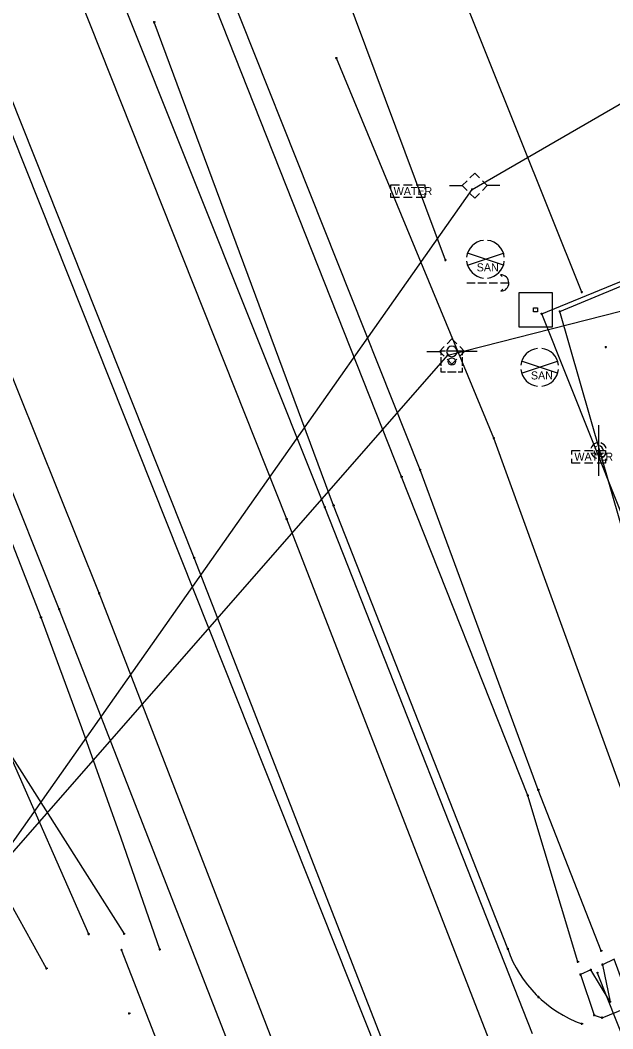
# Model space of a CAD drawing. Extents: x 1954856 to 2011933, y 399149 to 426294.
# Drawn here: x 2004898.7 to 2004969, y 408004.6 to 408124.3 of the extents above; entities that cross this region are included whole.
import ezdxf

# ---------------------------------------------------------------- set-up
doc = ezdxf.new("R2010")
doc.units = 0
for name, color, linetype in [('BankMent_ep', 7, 'Continuous'), ('BaselineSurvey', 7, 'Continuous'), ('ElecAer_ep', 7, 'Continuous'), ('EndTreatMES_ep', 7, 'Continuous'), ('Fence_ep', 7, 'Continuous'), ('FlowLineInvert_ep', 7, 'Continuous'), ('GuyWireAnchor_ep', 7, 'Continuous'), ('MeterWater_ep', 7, 'Continuous'), ('MonumentCC_ep', 7, 'Continuous'), ('PavtAsphalt_ep', 7, 'Continuous'), ('PavtAsphaltCrown_ep', 7, 'Continuous'), ('PipeCulvert_ep', 7, 'Continuous'), ('PointLocator_ep', 7, 'Continuous'), ('PoleElec_ep', 7, 'Continuous'), ('PoleShared_ep', 7, 'Continuous'), ('ShldrPaved_ep', 7, 'Continuous'), ('TelePed_ep', 7, 'Continuous'), ('TreeLineScatter_ep', 7, 'Continuous'), ('ValveCvrSewer_ep', 7, 'Continuous'), ('WaterFct_ep', 7, 'Continuous')]:
    doc.layers.add(name, color=color, linetype=linetype)

msp = doc.modelspace()

# ---------------------------------------------------------------- linework, layer by layer
at = {"layer": 'BankMent_ep'}
for p, q in [((2004935.85, 408066.75), (2004914.58, 408124.08)), ((2004954.86, 408074.74), (2004936.18, 408119.82)), ((2004974.42, 408020.72), (2004954.86, 408074.74)), ((2004956.5, 408014.12), (2004935.85, 408066.75)), ((2004901.81, 408011.79), (2004882.61, 408046.36))]:
    msp.add_line(p, q, dxfattribs=at)
for points in [[(2004915.23, 408014.06), (2004910.66, 408027.24), (2004905.98, 408040.37), (2004901.14, 408053.44), (2004893.86, 408072.1), (2004886.3, 408090.65), (2004878.58, 408109.14), (2004870.82, 408127.61), (2004863.14, 408146.12), (2004851.89, 408174.22), (2004840.96, 408202.44), (2004830.19, 408230.72)], [(2004967.6, 408013.9), (2004960.12, 408032.99), (2004946.12, 408070.97), (2004923.28, 408128.46)], [(2004964.83, 408012.59), (2004958.88, 408032.32), (2004943.91, 408070.15), (2004921.14, 408127.75)], [(2004977.16, 408039.32), (2004962.69, 408089.76), (2005001.33, 408105.83)], [(2004906.8, 408015.87), (2004897.29, 408037.55), (2004911.01, 408015.9)]]:
    msp.add_lwpolyline(points, dxfattribs=at)
msp.add_arc((2004970.17, 408018.84), 14.46, 199.0739, 250.3363, dxfattribs=at)
at = {"layer": 'BaselineSurvey'}
msp.add_line((2004967.71, 407935.04), (2004043.6, 410254.04), dxfattribs=at)
msp.add_line((2004967.71, 407935.04), (2004043.6, 410254.04), dxfattribs=at)
at = {"layer": 'ElecAer_ep'}
for points in [[(2004893.49, 408020.69), (2004952.29, 408104.24), (2005007.14, 408136)], [(2004893.49, 408020.69), (2004949.39, 408084.58), (2005015.19, 408101.35)], [(2004949.39, 408084.58), (2005015.19, 408101.35)]]:
    msp.add_lwpolyline(points, dxfattribs=at)
at = {"layer": 'EndTreatMES_ep'}
msp.add_lwpolyline([(2004969.12, 408012.89), (2004967.74, 408012.24), (2004968.65, 408007.83), (2004966.34, 408011.64), (2004965.13, 408011.07), (2004966.76, 408006.27), (2004967.69, 408005.95), (2004970.5, 408007.07), (2004970.89, 408008.05)], close=True, dxfattribs=at)
at = {"layer": 'Fence_ep'}
for points in [[(2004965.28, 408092.05), (2004946.37, 408139.38), (2004934.99, 408168.84), (2004909.94, 408231.83)], [(2004990.83, 408013.53), (2004960.53, 408089.49), (2005000.44, 408105.86)]]:
    msp.add_lwpolyline(points, dxfattribs=at)
at = {"layer": 'FlowLineInvert_ep'}
for p, q in [((2004910.78, 408013.92), (2004910.6, 408014.09)), ((2004910.78, 408014.09), (2004910.6, 408013.92)), ((2004910.69, 408014.01), (2004910.69, 408014.01)), ((2004967.23, 408011.16), (2004967.05, 408011.34)), ((2004967.23, 408011.34), (2004967.05, 408011.16)), ((2004967.14, 408011.25), (2004967.14, 408011.25))]:
    msp.add_line(p, q, dxfattribs=at)
at = {"layer": 'GuyWireAnchor_ep'}
for p, q in [((2004955.66, 408094.12), (2004955.85, 408093.93)), ((2004951.63, 408093.16), (2004952.63, 408093.16)), ((2004952.97, 408093.16), (2004953.97, 408093.16)), ((2004954.3, 408093.16), (2004955.3, 408093.16)), ((2004955.63, 408093.15), (2004956.63, 408093.15)), ((2004955.67, 408092.18), (2004955.91, 408092.41)), ((2004956.63, 408093.15), (2004956.63, 408093.15))]:
    msp.add_line(p, q, dxfattribs=at)
msp.add_arc((2004955.66, 408093.15), 0.973, 271.14, 90.0059, dxfattribs=at)
at = {"layer": 'MeterWater_ep'}
for p, q in [((2004944.65, 408104.04), (2004944.65, 408104.04)), ((2004966.1, 408072.53), (2004966.1, 408072.53))]:
    msp.add_line(p, q, dxfattribs=at)
for points in [[(2004942.65, 408104.29), (2004942.65, 408104.79), (2004943.65, 408104.79)], [(2004944.15, 408104.79), (2004945.15, 408104.79)], [(2004945.65, 408104.79), (2004946.65, 408104.79), (2004946.65, 408104.29)], [(2004943.65, 408103.29), (2004942.65, 408103.29), (2004942.65, 408103.79)], [(2004945.15, 408103.29), (2004944.15, 408103.29)], [(2004946.65, 408103.79), (2004946.65, 408103.29), (2004945.65, 408103.29)], [(2004964.1, 408072.78), (2004964.1, 408073.28), (2004965.1, 408073.28)], [(2004965.6, 408073.28), (2004966.6, 408073.28)], [(2004967.1, 408073.28), (2004968.1, 408073.28), (2004968.1, 408072.78)], [(2004965.1, 408071.78), (2004964.1, 408071.78), (2004964.1, 408072.28)], [(2004968.1, 408072.28), (2004968.1, 408071.78), (2004967.1, 408071.78)], [(2004966.6, 408071.78), (2004965.6, 408071.78)]]:
    msp.add_lwpolyline(points, dxfattribs=at)
at = {"layer": 'MonumentCC_ep'}
msp.add_line((2004959.81, 408089.96), (2004959.81, 408089.96), dxfattribs=at)
msp.add_lwpolyline([(2004957.81, 408087.95), (2004961.81, 408087.95), (2004961.81, 408091.96), (2004957.81, 408091.96), (2004957.81, 408087.95)], dxfattribs=at)
msp.add_lwpolyline([(2004959.57, 408089.72), (2004959.57, 408090.19), (2004960.04, 408090.19), (2004960.04, 408089.72)], close=True, dxfattribs=at)
at = {"layer": 'PavtAsphalt_ep'}
for p, q in [((2004966.77, 407971.27), (2004930.29, 408065.1)), ((2004944.14, 407963.12), (2004908.03, 408056.32))]:
    msp.add_line(p, q, dxfattribs=at)
for points in [[(2004930.29, 408065.1), (2004893.54, 408157.67), (2004856.38, 408250.56), (2004819.21, 408343.48), (2004782.13, 408435.87), (2004745.09, 408528.98), (2004708.04, 408621.61), (2004670.84, 408714.83), (2004634.43, 408807.2), (2004597.18, 408900.11), (2004560.23, 408993.39), (2004523.08, 409086.65), (2004486.25, 409179.55), (2004449.35, 409272.32), (2004412.41, 409364.96), (2004375.27, 409458.2), (2004338.19, 409550.48), (2004300.95, 409644.08)], [(2004908.03, 408056.32), (2004870.87, 408148.95), (2004833.86, 408242.04), (2004796.66, 408334.54), (2004759.71, 408427.58), (2004722.75, 408520.32), (2004685.7, 408613.32), (2004648.57, 408706.42), (2004611.45, 408799.43), (2004574.35, 408892.33), (2004537.27, 408984.58), (2004500.45, 409078.03), (2004463.69, 409171), (2004426.25, 409264.13), (2004389.64, 409356.86), (2004352.63, 409449.56), (2004314.97, 409542.01), (2004278.21, 409635.44)]]:
    msp.add_lwpolyline(points, dxfattribs=at)
at = {"layer": 'PavtAsphaltCrown_ep'}
msp.add_line((2004955.66, 407967.32), (2004919.3, 408060.52), dxfattribs=at)
msp.add_lwpolyline([(2004919.3, 408060.52), (2004882.31, 408153.48), (2004845.12, 408246.24), (2004807.96, 408339.12), (2004770.74, 408431.91), (2004733.82, 408525.03), (2004696.73, 408617.52), (2004659.9, 408710.76), (2004622.5, 408803.47), (2004585.74, 408896.22), (2004548.97, 408989.35), (2004511.74, 409082.34), (2004474.91, 409175.32), (2004437.75, 409268.1), (2004401.04, 409361.08), (2004363.75, 409453.88), (2004326.65, 409546.7), (2004289.56, 409639.69)], dxfattribs=at)
at = {"layer": 'PipeCulvert_ep'}
for points in [[(2004934.28, 407953.41), (2004910.69, 408014.01)], [(2004985.56, 407964.83), (2004967.14, 408011.25)]]:
    msp.add_lwpolyline(points, dxfattribs=at)
at = {"layer": 'PointLocator_ep'}
for p, q in [((2004914.71, 408124.08), (2004914.46, 408124.08)), ((2004914.58, 408123.96), (2004914.58, 408124.21)), ((2004914.58, 408124.08), (2004914.58, 408124.08)), ((2004936.3, 408119.82), (2004936.05, 408119.82)), ((2004936.18, 408119.7), (2004936.18, 408119.95)), ((2004936.18, 408119.82), (2004936.18, 408119.82)), ((2004952.42, 408104.24), (2004952.17, 408104.24)), ((2004952.29, 408104.11), (2004952.29, 408104.36)), ((2004952.29, 408104.24), (2004952.29, 408104.24)), ((2004949.25, 408095.86), (2004949, 408095.86)), ((2004949.12, 408095.73), (2004949.12, 408095.98)), ((2004949.12, 408095.86), (2004949.12, 408095.86)), ((2004965.28, 408091.93), (2004965.28, 408092.18)), ((2004965.41, 408092.05), (2004965.16, 408092.05)), ((2004965.28, 408092.05), (2004965.28, 408092.05)), ((2004962.81, 408089.76), (2004962.56, 408089.76)), ((2004962.69, 408089.64), (2004962.69, 408089.89)), ((2004962.69, 408089.76), (2004962.69, 408089.76)), ((2004960.65, 408089.49), (2004960.4, 408089.49)), ((2004960.53, 408089.36), (2004960.53, 408089.61)), ((2004960.53, 408089.49), (2004960.53, 408089.49)), ((2004968.26, 408085.53), (2004968.01, 408085.53)), ((2004968.13, 408085.41), (2004968.13, 408085.66)), ((2004968.13, 408085.53), (2004968.13, 408085.53)), ((2004949.51, 408084.58), (2004949.26, 408084.58)), ((2004949.39, 408084.45), (2004949.39, 408084.7)), ((2004949.39, 408084.58), (2004949.39, 408084.58)), ((2004954.99, 408074.74), (2004954.74, 408074.74)), ((2004954.86, 408074.61), (2004954.86, 408074.86)), ((2004954.86, 408074.74), (2004954.86, 408074.74)), ((2004946.24, 408070.97), (2004945.99, 408070.97)), ((2004946.12, 408070.85), (2004946.12, 408071.1)), ((2004946.12, 408070.97), (2004946.12, 408070.97)), ((2004944.04, 408070.15), (2004943.79, 408070.15)), ((2004943.91, 408070.03), (2004943.91, 408070.28)), ((2004943.91, 408070.15), (2004943.91, 408070.15)), ((2004934.94, 408066.54), (2004934.69, 408066.54)), ((2004934.81, 408066.41), (2004934.81, 408066.66)), ((2004934.81, 408066.54), (2004934.81, 408066.54)), ((2004935.98, 408066.75), (2004935.73, 408066.75)), ((2004935.85, 408066.63), (2004935.85, 408066.88)), ((2004935.85, 408066.75), (2004935.85, 408066.75)), ((2004930.41, 408065.1), (2004930.16, 408065.1)), ((2004930.29, 408064.98), (2004930.29, 408065.23)), ((2004930.29, 408065.1), (2004930.29, 408065.1)), ((2004919.43, 408060.52), (2004919.18, 408060.52)), ((2004919.3, 408060.4), (2004919.3, 408060.65)), ((2004919.3, 408060.52), (2004919.3, 408060.52)), ((2004908.16, 408056.32), (2004907.91, 408056.32)), ((2004908.03, 408056.19), (2004908.03, 408056.44)), ((2004908.03, 408056.32), (2004908.03, 408056.32)), ((2004903.42, 408054.42), (2004903.17, 408054.42)), ((2004903.29, 408054.3), (2004903.29, 408054.55)), ((2004903.29, 408054.42), (2004903.29, 408054.42)), ((2004901.26, 408053.44), (2004901.01, 408053.44)), ((2004901.14, 408053.32), (2004901.14, 408053.57)), ((2004901.14, 408053.44), (2004901.14, 408053.44)), ((2004959, 408032.32), (2004958.75, 408032.32)), ((2004958.88, 408032.19), (2004958.88, 408032.44)), ((2004958.88, 408032.32), (2004958.88, 408032.32)), ((2004960.25, 408032.99), (2004960, 408032.99)), ((2004960.12, 408032.86), (2004960.12, 408033.11)), ((2004960.12, 408032.99), (2004960.12, 408032.99)), ((2004906.92, 408015.87), (2004906.67, 408015.87)), ((2004906.8, 408015.74), (2004906.8, 408015.99)), ((2004906.8, 408015.87), (2004906.8, 408015.87)), ((2004911.14, 408015.9), (2004910.89, 408015.9)), ((2004911.01, 408015.78), (2004911.01, 408016.03)), ((2004911.01, 408015.9), (2004911.01, 408015.9)), ((2004915.36, 408014.06), (2004915.11, 408014.06)), ((2004915.23, 408013.93), (2004915.23, 408014.18)), ((2004915.23, 408014.06), (2004915.23, 408014.06)), ((2004956.63, 408014.12), (2004956.38, 408014.12)), ((2004956.5, 408013.99), (2004956.5, 408014.24)), ((2004956.5, 408014.12), (2004956.5, 408014.12)), ((2004967.73, 408013.9), (2004967.48, 408013.9)), ((2004967.6, 408013.77), (2004967.6, 408014.02)), ((2004967.6, 408013.9), (2004967.6, 408013.9)), ((2004964.96, 408012.59), (2004964.71, 408012.59)), ((2004964.83, 408012.46), (2004964.83, 408012.71)), ((2004964.83, 408012.59), (2004964.83, 408012.59)), ((2004967.87, 408012.24), (2004967.62, 408012.24)), ((2004967.74, 408012.12), (2004967.74, 408012.37)), ((2004967.74, 408012.24), (2004967.74, 408012.24)), ((2004901.94, 408011.79), (2004901.69, 408011.79)), ((2004901.81, 408011.67), (2004901.81, 408011.92)), ((2004901.81, 408011.79), (2004901.81, 408011.79)), ((2004965.25, 408011.07), (2004965, 408011.07)), ((2004965.13, 408010.94), (2004965.13, 408011.19)), ((2004965.13, 408011.07), (2004965.13, 408011.07)), ((2004966.47, 408011.64), (2004966.22, 408011.64)), ((2004966.34, 408011.51), (2004966.34, 408011.76)), ((2004966.34, 408011.64), (2004966.34, 408011.64)), ((2004960.28, 408008.41), (2004960.03, 408008.41)), ((2004960.15, 408008.29), (2004960.15, 408008.54)), ((2004960.15, 408008.41), (2004960.15, 408008.41)), ((2004968.77, 408007.83), (2004968.52, 408007.83)), ((2004968.65, 408007.7), (2004968.65, 408007.95)), ((2004968.65, 408007.83), (2004968.65, 408007.83)), ((2004911.74, 408006.45), (2004911.49, 408006.45)), ((2004911.61, 408006.32), (2004911.61, 408006.57)), ((2004911.61, 408006.45), (2004911.61, 408006.45)), ((2004966.89, 408006.27), (2004966.64, 408006.27)), ((2004966.76, 408006.15), (2004966.76, 408006.4)), ((2004966.76, 408006.27), (2004966.76, 408006.27)), ((2004967.69, 408005.83), (2004967.69, 408006.08)), ((2004965.43, 408005.23), (2004965.18, 408005.23)), ((2004965.31, 408005.1), (2004965.31, 408005.35)), ((2004965.31, 408005.23), (2004965.31, 408005.23)), ((2004967.82, 408005.95), (2004967.57, 408005.95)), ((2004967.69, 408005.95), (2004967.69, 408005.95))]:
    msp.add_line(p, q, dxfattribs=at)
at = {"layer": 'PoleElec_ep'}
for p, q in [((2004949.6, 408104.7), (2004951.1, 408104.7)), ((2004951.1, 408104.7), (2004951.67, 408105.27)), ((2004951.67, 408104.13), (2004951.1, 408104.7)), ((2004952.59, 408104.7), (2004952.59, 408104.7)), ((2004955.57, 408104.7), (2004954.07, 408104.7))]:
    msp.add_line(p, q, dxfattribs=at)
for points in [[(2004952.02, 408105.62), (2004952.59, 408106.19), (2004953.15, 408105.62)], [(2004953.51, 408105.27), (2004954.07, 408104.7), (2004953.51, 408104.13)], [(2004953.15, 408103.78), (2004952.59, 408103.21), (2004952.02, 408103.78)]]:
    msp.add_lwpolyline(points, dxfattribs=at)
at = {"layer": 'PoleShared_ep'}
for p, q in [((2004946.9, 408085.02), (2004948.4, 408085.02)), ((2004948.4, 408085.02), (2004948.96, 408085.59)), ((2004948.96, 408084.46), (2004948.4, 408085.02)), ((2004949.88, 408085.02), (2004949.88, 408085.02)), ((2004952.87, 408085.02), (2004951.37, 408085.02))]:
    msp.add_line(p, q, dxfattribs=at)
for points in [[(2004949.32, 408085.94), (2004949.88, 408086.51), (2004950.45, 408085.94)], [(2004950.81, 408085.59), (2004951.37, 408085.02), (2004950.8, 408084.45)], [(2004950.45, 408084.1), (2004949.88, 408083.53), (2004949.32, 408084.1)]]:
    msp.add_lwpolyline(points, dxfattribs=at)
for start, end in [(90, 270), (270, 90)]:
    msp.add_arc((2004949.88, 408085.02), 0.625, start, end, dxfattribs=at)
at = {"layer": 'ShldrPaved_ep'}
for p, q in [((2004934.81, 408066.54), (2004908.98, 408131.19)), ((2004959.44, 408004.04), (2004934.81, 408066.54)), ((2004924.26, 408000.63), (2004903.29, 408054.42))]:
    msp.add_line(p, q, dxfattribs=at)
msp.add_lwpolyline([(2004903.29, 408054.42), (2004866.25, 408147.18), (2004829.78, 408238.43), (2004819.43, 408264.53), (2004792.12, 408332.81), (2004764.06, 408411.25), (2004736.07, 408472.39), (2004723.51, 408503.89), (2004692.56, 408581.58), (2004685.95, 408598.81), (2004662.72, 408655.96), (2004643.53, 408704.54), (2004611.46, 408784.57), (2004586.66, 408847.41), (2004569.7, 408890.52), (2004561.67, 408910.22), (2004521.28, 409011.51), (2004496.04, 409076.36), (2004458.97, 409168.82), (2004421.59, 409262.3), (2004384.82, 409355.23), (2004347.84, 409447.99), (2004310.72, 409540.77), (2004273.84, 409633.55)], dxfattribs=at)
at = {"layer": 'TelePed_ep'}
for p, q in [((2004948.62, 408085.08), (2004949.12, 408085.08)), ((2004948.62, 408084.58), (2004948.62, 408085.08)), ((2004949.37, 408085.08), (2004950.37, 408085.08)), ((2004950.62, 408085.08), (2004951.12, 408085.08)), ((2004951.12, 408084.58), (2004951.12, 408085.08)), ((2004948.62, 408083.33), (2004948.62, 408084.33)), ((2004949.87, 408083.83), (2004949.87, 408083.83)), ((2004951.12, 408083.33), (2004951.12, 408084.33)), ((2004948.62, 408082.58), (2004948.62, 408083.08)), ((2004949.12, 408082.58), (2004948.62, 408082.58)), ((2004950.37, 408082.58), (2004949.37, 408082.58)), ((2004951.12, 408082.58), (2004950.62, 408082.58)), ((2004951.12, 408082.58), (2004951.12, 408083.08))]:
    msp.add_line(p, q, dxfattribs=at)
msp.add_circle((2004949.87, 408083.83), 0.438, dxfattribs=at)
at = {"layer": 'TreeLineScatter_ep'}
msp.add_lwpolyline([(2004949.12, 408095.86), (2004899.41, 408229.06)], dxfattribs=at)
at = {"layer": 'ValveCvrSewer_ep'}
for p, q in [((2004951.73, 408095.26), (2004955.99, 408096.68)), ((2004955.99, 408095.26), (2004951.73, 408096.68)), ((2004953.86, 408095.97), (2004953.86, 408095.97)), ((2004958.15, 408082.43), (2004962.42, 408083.85)), ((2004962.42, 408082.43), (2004958.15, 408083.85)), ((2004960.29, 408083.14), (2004960.29, 408083.14))]:
    msp.add_line(p, q, dxfattribs=at)
for centre, start, end in [((2004953.86, 408095.97), 96.3794, 173.6206), ((2004953.86, 408095.97), 6.3794, 83.6206), ((2004953.86, 408095.97), 186.3794, 263.6206), ((2004953.86, 408095.97), 276.3794, 353.6206), ((2004960.29, 408083.14), 96.3794, 173.6206), ((2004960.29, 408083.14), 6.3794, 83.6206), ((2004960.29, 408083.14), 186.3794, 263.6206), ((2004960.29, 408083.14), 276.3794, 353.6206)]:
    msp.add_arc(centre, 2.25, start, end, dxfattribs=at)
at = {"layer": 'WaterFct_ep'}
for p, q in [((2004967.28, 408076.26), (2004967.28, 408070.26)), ((2004967.28, 408073.26), (2004967.28, 408073.26))]:
    msp.add_line(p, q, dxfattribs=at)
for radius, start, end in [(0.937, 105.466, 164.534), (0.937, 195.466, 254.534), (0.562, 180, 243.6122), (0.562, 116.3878, 153.6122), (0.562, 0, 90), (0.562, 270, 333.6122), (0.937, 15.466, 74.534), (0.937, 285.466, 344.534)]:
    msp.add_arc((2004967.28, 408073.26), radius, start, end, dxfattribs=at)

# ---------------------------------------------------------------- texts
at = {"layer": 'MeterWater_ep'}
for p in [(2004942.97, 408103.57), (2004964.41, 408072.06)]:
    msp.add_text('WATER', height=0.95, dxfattribs=at).set_placement(p)
at = {"layer": 'ValveCvrSewer_ep'}
for p in [(2004952.82, 408094.53), (2004959.25, 408081.7)]:
    msp.add_text('SAN', height=0.95, dxfattribs=at).set_placement(p)

doc.saveas('drawing.dxf')
